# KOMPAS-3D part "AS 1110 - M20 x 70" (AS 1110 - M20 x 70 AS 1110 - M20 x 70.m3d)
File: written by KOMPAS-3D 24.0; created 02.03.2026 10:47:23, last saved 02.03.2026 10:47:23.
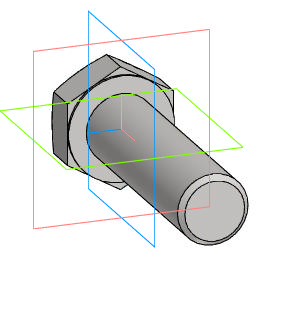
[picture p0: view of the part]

Document properties: Автор: R2D2; Полное имя файла: E:\Работа\Зайцев\GVWR3131M-2W-F-S Задвижка клиновая с выдвижным штоком DN.ru Ду50-200 Ру63\DN200\исходные материалы\AS 1110 - M20 x 70 AS 1110 - M20 x 70.m3d

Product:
- Body: Solid1  | qty 1
- Part/product: AS 1110 - M20 x 70
    Комментарий: Болты и винты   шестигранные точные   метрические ISO
    additional columns: Сталь, мягкая

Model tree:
1. Solid1  (labels: Solid1)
